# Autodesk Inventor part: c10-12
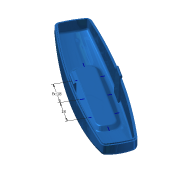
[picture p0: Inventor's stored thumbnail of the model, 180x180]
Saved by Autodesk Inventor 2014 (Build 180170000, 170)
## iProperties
Created: 2010-12
Part Number: c10-12
Material: Generic
Document SubType Name: Modeling
Designer: Thom Tremblay
Density: 1 g/cm^3
Appearance: Generic
Author: Thom Tremblay
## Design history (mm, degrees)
sketch "Sketch1"
  geometry: L1 (-60, -12)-(60, -12); L2 (60, -12)-(60, 12); L3 (60, 12)-(-60, 12); L4 (-60, 12)-(-60, -12); A1 r 350 centre (0, -332.819) between (60, 12) and (-60, 12); A2 r 350 centre (0, 332.819) between (-60, -12) and (60, -12); 3 further points
  constraints: 8 end point, 4 point on circle, 2 centre point, 2 midpoint, 2 parallel, 1 equal radius, 1 horizontal, 1 horizontal alignment, 1 perpendicular, 1 vertical alignment
  dimensions: "d0" = 120 distance of L3.end L2.end; "d1" = 24 distance of L2.end L1.end; "d2" = 350 radius of A1
workplane "Work Plane4"
sketch "Sketch5"
  geometry: L1 (-60, 12)-(-60, -12) reference; L2 (60, -12)-(60, 12) reference; L3 (-58, 10.314)-(-58, -10.314); L4 (58, -10.314)-(58, 10.314); A1 r 350 centre (0, 332.819) between (-60, -12) and (60, -12) reference; A2 r 350 centre (0, -332.819) between (60, 12) and (-60, 12) reference; A3 r 348 centre (0, 332.819) between (-58, -10.314) and (58, -10.314); A4 r 348 centre (0, -332.819) between (58, 10.314) and (-58, 10.314); 1 further point
  constraints: 4 end point, 4 point on circle, 2 centre point, 3 other
  dimensions: "d37" = 2 distance between parallel lines of L2 L4
sketch "Sketch6"
  geometry: L1 (-60, 0)-(60, 0); L2 (60, 0)-(58.843, 22.085); L3 (-60, 0)-(-58.779, 23.307); A1 r 691.758 centre (630.81, -36.204) between (-60, 0) and (-58, -100); A2 r 691.758 centre (-630.81, -36.204) between (58, -100) and (60, 0); 1 further point
  constraints: 6 end point, 4 point on circle, 2 centre point, 2 tangent, 1 horizontal
  dimensions: "d53" = 87 deg angle of L1 L3; "d54" = 87 deg angle of L1 L2 (= d53)
sketch "Sketch7"
  geometry: L1 (17.181, 0)-(12, 0) reference; L2 (15.181, -100)-(10.314, -100) reference; L3 (17.181, 0)-(16.768, 11.838); A1 r 911.322 centre (-893.585, -31.805) between (15.181, -100) and (17.181, 0); 1 further point
  constraints: 2 end point, 2 point on circle, 1 centre point, 1 tangent
  dimensions: "d56" = 88 deg angle of L1 L3
feature "LoftSrf2" sketch "Sketch5", "Sketch6", "Sketch7" dims "d57" = 0, "d58" = 90 deg, "d59" = 0, "d60" = 90 deg, "d61" = 0, "d62" = 90 deg, "d63" = 0, "d64" = 90 deg, "d65" = 0, "d66" = 90 deg
sketch "Sketch2"
  geometry: L1 (-75, -16)-(75, -16); L2 (-75, -60)-(75, -60); A1 r 183.781 centre (0, -183.781) between (75, -16) and (-75, -16); 2 further points
  constraints: 4 end point, 3 point on circle, 1 centre point, 1 coincident, 1 horizontal, 1 parallel
  dimensions: "d5" = 16 distance from line of point (0, 0) L1; "d7" = 60 distance from line of point (0, 0) L2; "d55" = 150 distance of L1.start L1.end
feature "RevolutionSrf1" sketch "Sketch2" dims angle "d8" = 40 deg
patch "Boundary Patch1" dims "d13" = 0, "d67" = 0, "d68" = 0, "d69" = 0, "d70" = 0
workplane "Work Plane1"
sketch "Sketch3"
  geometry: L1 (52, -85)-(52, -73); L2 (38, -73)-(38, -85); A1 r 7 centre (45, -73) between (52, -73) and (38, -73); A2 r 7 centre (45, -85) between (38, -85) and (52, -85); 1 further point
  constraints: 4 end point, 4 point on circle, 4 tangent, 2 centre point, 1 parallel, 1 vertical
  dimensions: "d15" = 12 distance of L1.start L1.end; "d16" = 7 radius of A1; "d50" = 45 horizontal distance of A1.centre point (0, 0); "d51" = 85 vertical distance of point (0, 0) A2.centre
extrude_surface "ExtrusionSrf2" sketch "Sketch3" dims "d19" = 14, "d20" = 5 deg
pattern_linear "Rectangular Pattern1" dims "d23" = 90
workplane "Work Plane2"
feature "Sculpt1"
sketch "Sketch4"
  geometry: L1 (-24.5, 6)-(24.5, 6); L2 (27.5, 3)-(27.5, -3); L3 (24.5, -6)-(-24.5, -6); L4 (-27.5, -3)-(-27.5, 3); A1 r 3 centre (-24.5, 3) between (-24.5, 6) and (-27.5, 3); A2 r 3 centre (24.5, 3) between (27.5, 3) and (24.5, 6); A3 r 3 centre (24.5, -3) between (24.5, -6) and (27.5, -3); A4 r 3 centre (-24.5, -3) between (-27.5, -3) and (-24.5, -6); 6 further points
  constraints: 8 end point, 8 point on circle, 8 tangent, 6 point on line, 4 centre point, 3 equal radius, 2 midpoint, 2 parallel, 1 horizontal, 1 horizontal alignment, 1 perpendicular, 1 vertical alignment
  dimensions: "d28" = 55 distance of point (27.5, -6) point (-27.5, -6); "d29" = 12 distance of point (27.5, 6) point (27.5, -6); "d30" = 3 radius of A1
extrude_surface "ExtrusionSrf6" sketch "Sketch4" dims "d31" = 14, "d32" = 45 deg
patch "Boundary Patch2" dims "d33" = 0, "d34" = 0
fillet "Fillet1" dims "d79" = 4, "d80" = 3, "d81" = 1
feature "Sculpt2"
node "Splitting Plane 1"
shell "Shell1" dims "d83" = 2
split "Split1"
  body "Solid1"
feature "Lip1" dims "d188" = 1, "d189" = 1, "d190" = 0, "d191" = 0, "d192" = 0, "d193" = 0
feature "Lip2" dims "d194" = 1, "d195" = 1, "d196" = 0, "d197" = 0, "d198" = 0, "d199" = 0.5
split "Split3"
  node "Back"
sketch "Sketch9"
  geometry: L1 (50.167, -73)-(50.167, -85) reference; L2 (39.833, -85)-(39.833, -73) reference; L3 (45, -73)-(45, -85); L4 (45, -85)-(39.833, -85); A1 r 5.167 centre (45, -73) between (50.167, -73) and (39.833, -73) reference; A2 r 5.167 centre (45, -85) between (39.833, -85) and (50.167, -85) reference; 5 further points
  constraints: 4 end point, 1 horizontal, 1 midpoint, 1 parallel, 1 perpendicular, 1 vertical, 3 other
  dimensions: "d86" = 90 distance of point (45, -79) point (-45, -79); "d89" = 40 distance of point (45, -79) point (45, -39)
  node "Projected Loop1"
feature "Boss1" dims "d92" = 0, "d93" = 0, "d94" = 7, "d95" = 2, "d96" = 0.5, "d97" = 6, "d98" = 1.25, "d99" = 3.5, "d100" = 2.5 deg, "d101" = 2.5 deg, "d102" = 2.5 deg, "d103" = 2.5 deg, "d104" = 90 deg, "d107" = 2, "d108" = 2, "d109" = 10, "d110" = 0, "d111" = 10 deg, "d112" = 2.5 deg, "d113" = 0, "d114" = 0, "d115" = 0, "d116" = 360 deg
feature "Boss2" dims "d117" = 3, "d118" = 0, "d119" = 6, "d120" = 3, "d121" = 9.5, "d122" = 2 deg, "d123" = 1 deg, "d126" = 2, "d127" = 2, "d128" = 10, "d129" = 0, "d130" = 10 deg, "d131" = 2.5 deg, "d132" = 0, "d133" = 0, "d134" = 0, "d135" = 360 deg
workplane "Work Plane6"
sketch "Sketch10"
  geometry: L1 (24, -85)-(-24, -85); L2 (-30, -79)-(-30, -51); L3 (-24, -45)-(24, -45); L4 (30, -51)-(30, -79); L5 (54.344, -100)-(-54.344, -100) reference; A1 r 6 centre (-24, -51) between (-24, -45) and (-30, -51); A2 r 6 centre (24, -51) between (30, -51) and (24, -45); A3 r 6 centre (24, -79) between (24, -85) and (30, -79); A4 r 6 centre (-24, -79) between (-30, -79) and (-24, -85); 5 further points
  constraints: 8 end point, 8 point on circle, 8 tangent, 6 point on line, 4 centre point, 3 equal radius, 2 parallel, 1 horizontal, 1 midpoint, 1 perpendicular, 1 vertical alignment
  dimensions: "d137" = 60 distance of point (-30, -45) point (30, -45); "d138" = 40 distance of point (-30, -85) point (-30, -45); "d139" = 15 distance between parallel lines of L5 L1; "d141" = 6 radius of A2
feature "Rest1" sketch "Sketch10" dims "d142" = 5, "d143" = 0, "d144" = 0, "d145" = 0, "d146" = 2 deg, "d147" = 2 deg, "d148" = 2
feature "Rule Fillet1" dims "d149" = 2, "d150" = 1
workplane "Work Plane7"
sketch "Sketch11" dims "d154" = 16, "d155" = 8, "d161" = 10, "d168" = 10
  geometry: L1 (-13, -39.858)-(-13, -90.142); L2 (-25.187, -85)-(29.449, -85); L3 (0, -39.858)-(0, -90.142); L4 (13, -39.858)-(13, -90.142); L5 (-25.187, -77)-(29.449, -77); L6 (-25.187, -69)-(29.449, -69); L7 (-25.187, -61)-(29.449, -61); L8 (-25.187, -53)-(29.449, -53); L9 (-25.187, -45)-(29.449, -45); C1 r 22.5 at (0, -65); 3 further points; 1 other entity
  constraints: 18 end point, 2 coincident, 2 vertical, 1 centre point, 1 horizontal, 1 midpoint, 1 perpendicular, 1 vertical alignment, 23 other
  dimensions: "d152" = 45 diameter of C1; "d153" = 65 distance of point (0, 0) C1.centre; "d158" = 13 distance of L1.start L3.start; "d165" = 8 distance of L2.start L5.start; "d170" = 4 distance from line of L7 point (0, -65)
feature "Grill1" sketch "Sketch11" dims "d173" = 2, "d174" = 0, "d175" = 1, "d176" = 2, "d177" = 0, "d178" = 1, "d179" = 0.5, "d180" = 0, "d181" = 2, "d182" = 1, "d183" = 2 deg, "d184" = 0, "d185" = 88.84492
sketch "Sketch12"
  geometry: L1 (-12.481, -61.203)-(12.401, -61.203); L2 (12.401, -61.203)-(12.401, -68.714); L3 (12.401, -68.714)-(-12.481, -68.714); L4 (-12.481, -68.714)-(-12.481, -61.203); 1 further point
  constraints: 2 other
emboss "Emboss1" sketch "Sketch12" dims "d186" = 0.5, "d187" = 0
sketch "Sketch13"
  geometry: L1 (0, 15.66)-(0, -14.781); 6 further points
  constraints: 2 end point, 1 coincident, 1 point on line, 1 vertical, 4 other
feature "Snap Fit1" sketch "Sketch13" dims "d200" = 4, "d201" = 2.5, "d202" = 1, "d203" = 0.9, "d204" = 10.2, "d205" = 10, "d206" = 1, "d207" = 1, "d208" = 50 deg, "d209" = 50 deg
fillet "Fillet2" dims "d213" = 2
workplane "Work Plane8"
sketch "Sketch14"
  geometry: L1 (-8.644, -6.828)-(57.644, -6.828); L2 (6.5, 3.689)-(6.5, -17.346); L3 (24.5, 3.689)-(24.5, -17.346); L4 (42.5, 3.689)-(42.5, -17.346); 2 further points
  constraints: 8 end point, 4 parallel, 2 horizontal alignment, 2 midpoint, 1 coincident, 1 horizontal, 1 perpendicular
  dimensions: "d211" = 18 distance between parallel lines of L3 L2; "d212" = 18 distance between parallel lines of L4 L3 (= d211)
body "Srf2"
body "Srf3"
body "Srf4"
body "Srf5"
body "Srf6"
body "Srf7"
body "Srf8"
body "Srf9"
body "Srf11"
feature "Stitch Surface1"
body "Srf12"
extrude_surface "ExtrusionSrf3"
extrude_surface "ExtrusionSrf4"
extrude_surface "ExtrusionSrf5"
node "Front"
node "Back - Top"
node "Back - Bottom"
other parameters: "d14" = -24, "d52" = -6, "d171" = 1, "d172" = 2, "d210" = -1
